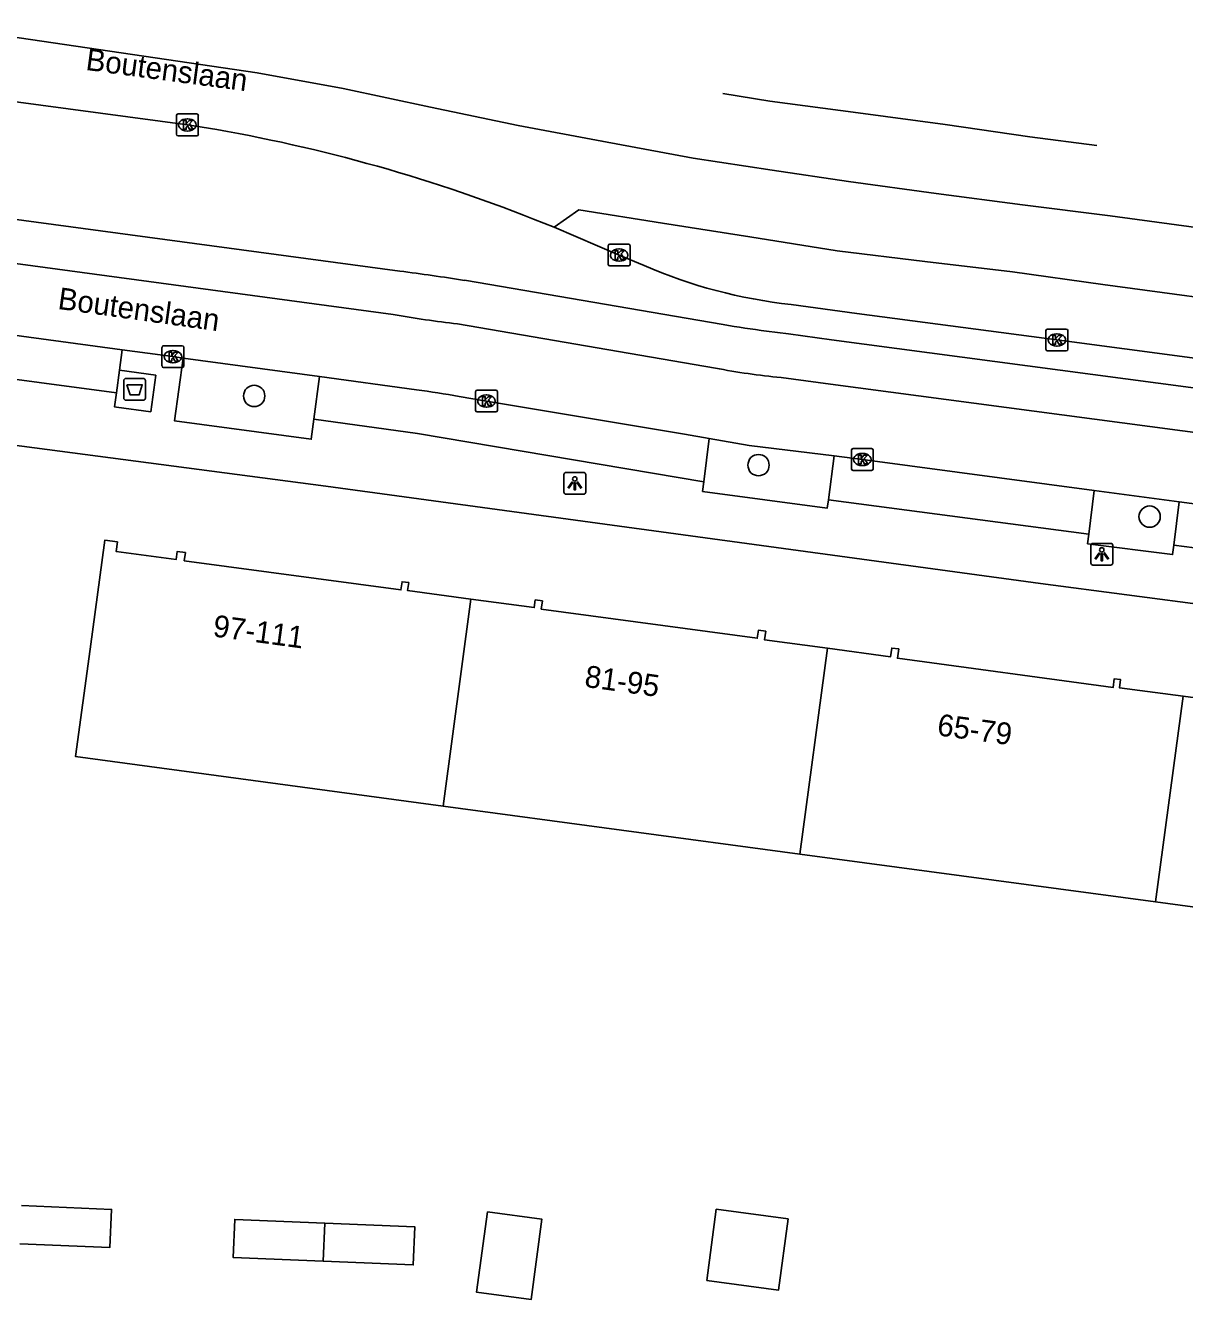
# Model space of a CAD drawing. Extents: x 161258 to 161838, y 380836 to 381727.
# Drawn here: x 161670.2 to 161723.3, y 381612.4 to 381670.8 of the extents above; entities that cross this region are included whole.
import ezdxf

# ---------------------------------------------------------------- set-up
doc = ezdxf.new("R2010")
doc.units = 0
for name, color, linetype in [('IMGEO_Afval_apart_plaats', 7, 'Continuous'), ('IMGEO_Boom', 7, 'Continuous'), ('IMGEO_Kolk', 7, 'Continuous'), ('IMGEO_Lichtpunt', 7, 'Continuous'), ('IMGEO_Openbare_ruimte_label', 7, 'Continuous'), ('IMGEO_Pand', 7, 'Continuous'), ('IMGEO_Pand_nummerreeks', 7, 'Continuous'), ('IMGEO_Parkeervlak_halfverhard', 7, 'Continuous'), ('IMGEO_Parkeervlak_open', 7, 'Continuous'), ('IMGEO_Rijbaan_lokaal_open', 7, 'Continuous'), ('IMGEO_Rijbaan_regionaal_gesloten', 7, 'Continuous'), ('IMGEO_Voetpad_gesloten', 7, 'Continuous'), ('IMGEO_Voetpad_open', 7, 'Continuous')]:
    doc.layers.add(name, color=color, linetype=linetype)

msp = doc.modelspace()

# ---------------------------------------------------------------- linework, layer by layer
at = {"layer": 'IMGEO_Afval_apart_plaats'}
for p, q in [((161674.752, 381653.736), (161674.752, 381654.536)), ((161674.752, 381654.536), (161674.752, 381653.736)), ((161674.852, 381654.636), (161675.642, 381654.636)), ((161675.642, 381654.636), (161674.852, 381654.636)), ((161675.742, 381654.536), (161675.742, 381653.736)), ((161675.742, 381653.736), (161675.742, 381654.536)), ((161675.642, 381653.636), (161674.852, 381653.636)), ((161674.852, 381653.636), (161675.642, 381653.636))]:
    msp.add_line(p, q, dxfattribs=at)
msp.add_lwpolyline([(161674.895, 381654.35), (161675.599, 381654.35), (161675.45, 381653.88), (161675.044, 381653.88), (161674.895, 381654.35)], dxfattribs=at)
for centre, start, end in [((161674.852, 381654.536), 90, 180), ((161674.852, 381654.536), 90, 180), ((161675.642, 381654.536), 0, 90), ((161675.642, 381654.536), 360, 90), ((161674.852, 381653.736), 180, 270), ((161674.852, 381653.736), 180, 270), ((161675.642, 381653.736), 270, 0), ((161675.642, 381653.736), 270, 0)]:
    msp.add_arc(centre, 0.1, start, end, dxfattribs=at)
at = {"layer": 'IMGEO_Boom'}
for centre in [(161680.724, 381653.834), (161703.825, 381650.663), (161721.741, 381648.304)]:
    msp.add_circle(centre, 0.489, dxfattribs=at)
at = {"layer": 'IMGEO_Kolk'}
for p, q in [((161677.165, 381665.828), (161677.165, 381666.68)), ((161677.24, 381666.754), (161678.092, 381666.754)), ((161678.166, 381666.68), (161678.166, 381665.828)), ((161677.653, 381666.534), (161677.678, 381666.534)), ((161678.092, 381665.754), (161677.24, 381665.754)), ((161677.676, 381665.974), (161677.651, 381665.974)), ((161696.94, 381659.864), (161696.94, 381660.716)), ((161697.015, 381660.79), (161697.867, 381660.79)), ((161697.428, 381660.57), (161697.453, 381660.57)), ((161697.941, 381660.716), (161697.941, 381659.864)), ((161697.867, 381659.79), (161697.015, 381659.79)), ((161697.451, 381660.01), (161697.426, 381660.01)), ((161716.992, 381655.974), (161716.992, 381656.826)), ((161717.067, 381656.9), (161717.919, 381656.9)), ((161717.993, 381656.826), (161717.993, 381655.974)), ((161717.48, 381656.68), (161717.505, 381656.68)), ((161676.502, 381655.209), (161676.502, 381656.061)), ((161676.577, 381656.135), (161677.429, 381656.135)), ((161676.99, 381655.915), (161677.015, 381655.915)), ((161677.503, 381656.061), (161677.503, 381655.209)), ((161717.919, 381655.9), (161717.067, 381655.9)), ((161717.503, 381656.12), (161717.478, 381656.12)), ((161677.429, 381655.135), (161676.577, 381655.135)), ((161677.013, 381655.355), (161676.988, 381655.355)), ((161690.863, 381653.174), (161690.863, 381654.026)), ((161690.938, 381654.1), (161691.79, 381654.1)), ((161691.351, 381653.88), (161691.376, 381653.88)), ((161691.864, 381654.026), (161691.864, 381653.174)), ((161691.374, 381653.32), (161691.349, 381653.32)), ((161691.79, 381653.1), (161690.938, 381653.1)), ((161708.08, 381650.497), (161708.08, 381651.349)), ((161708.155, 381651.423), (161709.007, 381651.423)), ((161708.568, 381651.203), (161708.593, 381651.203)), ((161709.081, 381651.349), (161709.081, 381650.497)), ((161709.007, 381650.423), (161708.155, 381650.423)), ((161708.591, 381650.643), (161708.566, 381650.643))]:
    msp.add_line(p, q, dxfattribs=at)
for points in [[(161677.165, 381665.828), (161677.165, 381666.68)], [(161677.24, 381666.754), (161678.092, 381666.754)], [(161678.166, 381666.68), (161678.166, 381665.828)], [(161677.486, 381666.454), (161677.609, 381666.454), (161677.609, 381666.303), (161677.739, 381666.454), (161677.903, 381666.454), (161677.757, 381666.303), (161677.91, 381666.054), (161677.758, 381666.054), (161677.673, 381666.218), (161677.609, 381666.151), (161677.609, 381666.054), (161677.486, 381666.054), (161677.486, 381666.454)], [(161678.092, 381665.754), (161677.24, 381665.754)], [(161696.94, 381659.864), (161696.94, 381660.716)], [(161697.015, 381660.79), (161697.867, 381660.79)], [(161697.261, 381660.49), (161697.384, 381660.49), (161697.384, 381660.339), (161697.514, 381660.49), (161697.678, 381660.49), (161697.532, 381660.339), (161697.685, 381660.09), (161697.533, 381660.09), (161697.448, 381660.254), (161697.384, 381660.187), (161697.384, 381660.09), (161697.261, 381660.09), (161697.261, 381660.49)], [(161697.941, 381660.716), (161697.941, 381659.864)], [(161697.867, 381659.79), (161697.015, 381659.79)], [(161716.992, 381655.974), (161716.992, 381656.826)], [(161717.067, 381656.9), (161717.919, 381656.9)], [(161717.993, 381656.826), (161717.993, 381655.974)], [(161717.313, 381656.6), (161717.436, 381656.6), (161717.436, 381656.449), (161717.566, 381656.6), (161717.73, 381656.6), (161717.584, 381656.449), (161717.737, 381656.2), (161717.585, 381656.2), (161717.5, 381656.364), (161717.436, 381656.297), (161717.436, 381656.2), (161717.313, 381656.2), (161717.313, 381656.6)], [(161676.502, 381655.209), (161676.502, 381656.061)], [(161676.577, 381656.135), (161677.429, 381656.135)], [(161676.823, 381655.835), (161676.946, 381655.835), (161676.946, 381655.684), (161677.076, 381655.835), (161677.24, 381655.835), (161677.094, 381655.684), (161677.247, 381655.435), (161677.095, 381655.435), (161677.01, 381655.599), (161676.946, 381655.532), (161676.946, 381655.435), (161676.823, 381655.435), (161676.823, 381655.835)], [(161677.503, 381656.061), (161677.503, 381655.209)], [(161717.919, 381655.9), (161717.067, 381655.9)], [(161677.429, 381655.135), (161676.577, 381655.135)], [(161690.863, 381653.174), (161690.863, 381654.026)], [(161690.938, 381654.1), (161691.79, 381654.1)], [(161691.864, 381654.026), (161691.864, 381653.174)], [(161691.184, 381653.8), (161691.307, 381653.8), (161691.307, 381653.649), (161691.437, 381653.8), (161691.601, 381653.8), (161691.455, 381653.649), (161691.608, 381653.4), (161691.456, 381653.4), (161691.371, 381653.564), (161691.307, 381653.497), (161691.307, 381653.4), (161691.184, 381653.4), (161691.184, 381653.8)], [(161691.79, 381653.1), (161690.938, 381653.1)], [(161708.08, 381650.497), (161708.08, 381651.349)], [(161708.155, 381651.423), (161709.007, 381651.423)], [(161708.401, 381651.123), (161708.524, 381651.123), (161708.524, 381650.972), (161708.654, 381651.123), (161708.818, 381651.123), (161708.672, 381650.972), (161708.825, 381650.723), (161708.673, 381650.723), (161708.588, 381650.887), (161708.524, 381650.82), (161708.524, 381650.723), (161708.401, 381650.723), (161708.401, 381651.123)], [(161709.081, 381651.349), (161709.081, 381650.497)], [(161709.007, 381650.423), (161708.155, 381650.423)]]:
    msp.add_lwpolyline(points, dxfattribs=at)
for centre, start, end in [((161677.242, 381666.678), 91.55205, 178.44795), ((161677.242, 381666.678), 91.55205, 178.44795), ((161678.09, 381666.678), 1.55205, 88.44795), ((161678.09, 381666.678), 1.55205, 88.44795), ((161677.242, 381665.83), 181.55205, 268.44795), ((161677.242, 381665.83), 181.55205, 268.44795), ((161678.09, 381665.83), 271.55205, 358.44795), ((161678.09, 381665.83), 271.55205, 358.44795), ((161697.017, 381660.714), 91.55205, 178.44795), ((161697.017, 381660.714), 91.55205, 178.44795), ((161697.865, 381660.714), 1.55205, 88.44795), ((161697.865, 381660.714), 1.55205, 88.44795), ((161697.017, 381659.866), 181.55205, 268.44795), ((161697.017, 381659.866), 181.55205, 268.44795), ((161697.865, 381659.866), 271.55205, 358.44795), ((161697.865, 381659.866), 271.55205, 358.44795), ((161717.069, 381656.824), 91.55205, 178.44795), ((161717.069, 381656.824), 91.55205, 178.44795), ((161717.917, 381656.824), 1.55205, 88.44795), ((161717.917, 381656.824), 1.55205, 88.44795), ((161676.579, 381656.059), 91.55205, 178.44795), ((161676.579, 381656.059), 91.55205, 178.44795), ((161677.427, 381656.059), 1.55205, 88.44795), ((161677.427, 381656.059), 1.55205, 88.44795), ((161717.069, 381655.976), 181.55205, 268.44795), ((161717.069, 381655.976), 181.55205, 268.44795), ((161717.917, 381655.976), 271.55205, 358.44795), ((161717.917, 381655.976), 271.55205, 358.44795), ((161676.579, 381655.211), 181.55205, 268.44795), ((161676.579, 381655.211), 181.55205, 268.44795), ((161677.427, 381655.211), 271.55205, 358.44795), ((161677.427, 381655.211), 271.55205, 358.44795), ((161690.94, 381654.024), 91.55205, 178.44795), ((161690.94, 381654.024), 91.55205, 178.44795), ((161691.788, 381654.024), 1.55205, 88.44795), ((161691.788, 381654.024), 1.55205, 88.44795), ((161690.94, 381653.176), 181.55205, 268.44795), ((161690.94, 381653.176), 181.55205, 268.44795), ((161691.788, 381653.176), 271.55205, 358.44795), ((161691.788, 381653.176), 271.55205, 358.44795), ((161708.157, 381651.347), 91.55205, 178.44795), ((161708.157, 381651.347), 91.55205, 178.44795), ((161709.005, 381651.347), 1.55205, 88.44795), ((161709.005, 381651.347), 1.55205, 88.44795), ((161708.157, 381650.499), 181.55205, 268.44795), ((161708.157, 381650.499), 181.55205, 268.44795), ((161709.005, 381650.499), 271.55205, 358.44795), ((161709.005, 381650.499), 271.55205, 358.44795)]:
    msp.add_arc(centre, 0.0765, start, end, dxfattribs=at)
for centre, major_axis, ratio, start_param, end_param in [((161677.652, 381666.254), (-0.387, 0.002), 0.722429, 4.712389, 7.853982), ((161677.677, 381666.254), (-0.39, 0.002), 0.717154, 1.570796, 4.712389), ((161697.427, 381660.29), (-0.387, 0.002), 0.722429, 4.712389, 7.853982), ((161697.452, 381660.29), (-0.39, 0.002), 0.717154, 1.570796, 4.712389), ((161717.479, 381656.4), (-0.387, 0.002), 0.722429, 4.712389, 7.853982), ((161717.504, 381656.4), (-0.39, 0.002), 0.717154, 1.570796, 4.712389), ((161676.989, 381655.635), (-0.387, 0.002), 0.722429, 4.712389, 7.853982), ((161677.014, 381655.635), (-0.39, 0.002), 0.717154, 1.570796, 4.712389), ((161691.35, 381653.6), (-0.387, 0.002), 0.722429, 4.712389, 7.853982), ((161691.375, 381653.6), (-0.39, 0.002), 0.717154, 1.570796, 4.712389), ((161708.567, 381650.923), (-0.387, 0.002), 0.722429, 4.712389, 7.853982), ((161708.592, 381650.923), (-0.39, 0.002), 0.717154, 1.570796, 4.712389)]:
    msp.add_ellipse(centre, major_axis=major_axis, ratio=ratio, start_param=start_param, end_param=end_param, dxfattribs=at)
at = {"layer": 'IMGEO_Lichtpunt'}
for p, q in [((161694.912, 381650.235), (161694.912, 381649.428)), ((161694.912, 381650.235), (161694.912, 381649.428)), ((161695.814, 381650.33), (161695.006, 381650.33)), ((161695.814, 381650.33), (161695.006, 381650.33)), ((161695.908, 381649.428), (161695.908, 381650.235)), ((161695.908, 381649.428), (161695.908, 381650.235)), ((161695.006, 381649.334), (161695.814, 381649.334)), ((161695.006, 381649.334), (161695.814, 381649.334)), ((161719.051, 381646.984), (161719.051, 381646.177)), ((161719.051, 381646.984), (161719.051, 381646.177)), ((161719.953, 381647.079), (161719.145, 381647.079)), ((161719.953, 381647.079), (161719.145, 381647.079)), ((161720.047, 381646.177), (161720.047, 381646.984)), ((161720.047, 381646.177), (161720.047, 381646.984)), ((161719.145, 381646.083), (161719.953, 381646.083)), ((161719.145, 381646.083), (161719.953, 381646.083))]:
    msp.add_line(p, q, dxfattribs=at)
for points in [[(161695.286, 381649.899), (161695.325, 381649.871), (161695.137, 381649.609), (161695.099, 381649.636), (161695.286, 381649.899)], [(161695.388, 381649.851), (161695.435, 381649.851), (161695.435, 381649.529), (161695.388, 381649.529), (161695.388, 381649.851)], [(161695.498, 381649.871), (161695.536, 381649.898), (161695.723, 381649.636), (161695.684, 381649.608), (161695.498, 381649.871)], [(161719.425, 381646.648), (161719.464, 381646.62), (161719.276, 381646.358), (161719.238, 381646.385), (161719.425, 381646.648)], [(161719.527, 381646.6), (161719.574, 381646.6), (161719.574, 381646.278), (161719.527, 381646.278), (161719.527, 381646.6)], [(161719.637, 381646.62), (161719.675, 381646.647), (161719.862, 381646.385), (161719.823, 381646.357), (161719.637, 381646.62)]]:
    msp.add_lwpolyline(points, dxfattribs=at)
for centre in [(161695.411, 381650.033), (161719.55, 381646.782)]:
    msp.add_circle(centre, 0.0994, dxfattribs=at)
for centre, start, end in [((161695.006, 381650.235), 90, 180), ((161695.006, 381650.235), 90, 180), ((161695.814, 381650.235), 0, 90), ((161695.814, 381650.235), 0, 90), ((161695.006, 381649.428), 180, 270), ((161695.006, 381649.428), 180, 270), ((161695.814, 381649.428), 270, 0), ((161695.814, 381649.428), 270, 360), ((161719.145, 381646.984), 90, 180), ((161719.145, 381646.984), 90, 180), ((161719.953, 381646.984), 0, 90), ((161719.953, 381646.984), 0, 90), ((161719.145, 381646.177), 180, 270), ((161719.145, 381646.177), 180, 270), ((161719.953, 381646.177), 270, 0), ((161719.953, 381646.177), 270, 360)]:
    msp.add_arc(centre, 0.0946, start, end, dxfattribs=at)
at = {"layer": 'IMGEO_Pand'}
for points in [[(161689.376, 381635.044), (161672.547, 381637.31), (161673.211, 381642.236), (161673.883, 381647.225), (161674.458, 381647.147), (161674.399, 381646.707), (161677.147, 381646.337), (161677.197, 381646.707), (161677.574, 381646.656), (161677.524, 381646.282), (161687.447, 381644.945), (161687.498, 381645.32), (161687.801, 381645.279), (161687.752, 381644.918), (161690.653, 381644.528)], [(161690.653, 381644.528), (161689.376, 381635.044)], [(161690.653, 381644.528), (161693.554, 381644.137), (161693.602, 381644.489), (161693.926, 381644.446), (161693.874, 381644.065), (161703.771, 381642.732), (161703.82, 381643.1), (161704.157, 381643.055), (161704.104, 381642.658), (161706.989, 381642.27)], [(161706.989, 381642.27), (161705.72, 381632.842)], [(161706.989, 381642.27), (161709.875, 381641.881), (161709.929, 381642.284), (161710.245, 381642.241), (161710.187, 381641.813), (161720.07, 381640.482), (161720.122, 381640.875), (161720.407, 381640.837), (161720.357, 381640.466), (161723.281, 381640.073)], [(161723.281, 381640.073), (161726.205, 381639.679), (161726.266, 381640.131), (161726.654, 381640.079), (161726.594, 381639.634), (161736.456, 381638.306), (161736.51, 381638.705), (161736.829, 381638.662), (161736.776, 381638.265), (161739.537, 381637.893), (161739.596, 381638.332), (161740.038, 381638.273), (161738.708, 381628.4), (161733.754, 381629.067), (161722.012, 381630.648)], [(161722.012, 381630.648), (161723.281, 381640.073)], [(161705.72, 381632.842), (161689.376, 381635.044)], [(161722.012, 381630.648), (161705.72, 381632.842)], [(161670.067, 381616.733), (161674.192, 381616.563), (161674.12, 381614.818), (161669.995, 381614.987)], [(161701.453, 381613.302), (161704.739, 381612.86), (161705.179, 381616.129), (161701.893, 381616.571), (161701.453, 381613.302)], [(161683.883, 381614.19), (161679.759, 381614.359), (161679.831, 381616.104), (161683.955, 381615.935)], [(161683.955, 381615.935), (161688.08, 381615.765), (161688.009, 381614.02), (161683.883, 381614.19)], [(161683.955, 381615.935), (161683.883, 381614.19)], [(161691.406, 381616.447), (161693.905, 381616.111), (161693.41, 381612.432), (161690.912, 381612.768), (161691.406, 381616.447)]]:
    msp.add_lwpolyline(points, dxfattribs=at)
at = {"layer": 'IMGEO_Parkeervlak_halfverhard'}
for points in [[(161591.581, 381672.404), (161665.053, 381662.56), (161687.397, 381659.556)], [(161690.364, 381659.132), (161702.211, 381657.106)], [(161704.19, 381656.809), (161705.202, 381656.678), (161707.162, 381656.402), (161745.844, 381651.267), (161745.561, 381649.28)]]:
    msp.add_lwpolyline(points, dxfattribs=at)
for centre, radius, start, end in [((161668.394, 381515.989), 144.819, 81.27429, 82.4601), ((161709.103, 381696.289), 39.785, 260.02386, 262.90612)]:
    msp.add_arc(centre, radius, start, end, dxfattribs=at)
at = {"layer": 'IMGEO_Parkeervlak_open'}
for points in [[(161683.714, 381654.721), (161683.461, 381652.77)], [(161701.316, 381649.903), (161701.559, 381651.889)], [(161707.027, 381649.08), (161707.291, 381651.084)], [(161718.952, 381647.508), (161719.195, 381649.505)], [(161723.091, 381648.984), (161722.845, 381647.001)]]:
    msp.add_lwpolyline(points, dxfattribs=at)
at = {"layer": 'IMGEO_Rijbaan_lokaal_open'}
for points in [[(161687.091, 381657.568), (161667.513, 381660.211)], [(161667.573, 381656.908), (161674.685, 381655.948)], [(161701.851, 381655.11), (161690.043, 381657.133)], [(161674.685, 381655.948), (161677.003, 381655.635), (161677.476, 381655.571)], [(161677.476, 381655.571), (161683.714, 381654.721)], [(161683.714, 381654.721), (161688.152, 381654.117)], [(161743.167, 381649.597), (161707.129, 381654.372), (161704.858, 381654.679)], [(161690.111, 381653.815), (161691.364, 381653.6), (161700.442, 381652.083), (161701.559, 381651.889)], [(161701.559, 381651.889), (161703.394, 381651.569), (161707.291, 381651.084)], [(161707.291, 381651.084), (161708.581, 381650.923), (161719.195, 381649.505)], [(161719.195, 381649.505), (161723.091, 381648.984)], [(161723.091, 381648.984), (161723.895, 381648.877), (161734.952, 381647.415)]]:
    msp.add_lwpolyline(points, dxfattribs=at)
for centre, radius, start, end in [((161696.347, 381710.147), 53.388, 260.01599, 263.21871), ((161707.649, 381684.859), 30.309, 258.97077, 264.71568), ((161680.11, 381595.444), 59.222, 80.27738, 82.19514)]:
    msp.add_arc(centre, radius, start, end, dxfattribs=at)
at = {"layer": 'IMGEO_Rijbaan_regionaal_gesloten'}
for points in [[(161679.007, 381666.04), (161677.666, 381666.255), (161657.266, 381668.988), (161618.127, 381674.239), (161615.451, 381674.598), (161596.053, 381677.191), (161575.643, 381679.932), (161555.208, 381682.652), (161534.802, 381685.416), (161514.402, 381688.138), (161500, 381690.051), (161493.724, 381690.885), (161474.493, 381693.446), (161433.673, 381698.93), (161413.286, 381701.641), (161412.199, 381701.786)], [(161668.901, 381670.395), (161680.859, 381668.646), (161684.795, 381667.916), (161688.805, 381667.074), (161692.816, 381666.233), (161696.656, 381665.513), (161700.839, 381664.728), (161704.447, 381664.184), (161707.95, 381663.655), (161711.965, 381663.118), (161715.913, 381662.59), (161719.934, 381662.085), (161723.875, 381661.551), (161728.04, 381661.015), (161732.012, 381660.466), (161735.99, 381659.958), (161752.017, 381657.797), (161760.062, 381656.742)], [(161702.189, 381667.689), (161704.351, 381667.34), (161708.386, 381666.804), (161712.371, 381666.274), (161716.253, 381665.701), (161719.327, 381665.313)], [(161817.985, 381645.977), (161809.404, 381647.011), (161803.595, 381647.872), (161795.685, 381648.9), (161787.775, 381649.927), (161779.72, 381650.974), (161771.676, 381652.109), (161763.62, 381653.148), (161755.563, 381654.187), (161747.855, 381655.181), (161741.235, 381656.106), (161737.26, 381656.662), (161731.03, 381657.39), (161727.522, 381657.865), (161719.602, 381658.939), (161715.452, 381659.519), (161711.437, 381660.002), (161707.421, 381660.485), (161703.427, 381661.121), (161699.432, 381661.756), (161695.592, 381662.368), (161694.46, 381661.561)], [(161698.584, 381659.806), (161697.441, 381660.29), (161694.46, 381661.561)], [(161751.562, 381651.859), (161748.27, 381652.294), (161735.854, 381653.957), (161717.493, 381656.402), (161708.326, 381657.615), (161705.319, 381658.026)]]:
    msp.add_lwpolyline(points, dxfattribs=at)
for centre, radius, start, end in [((161666.124, 381592.694), 74.469, 67.63445, 80.03744), ((161707.843, 381681.209), 23.32, 246.60568, 263.78579)]:
    msp.add_arc(centre, radius, start, end, dxfattribs=at)
at = {"layer": 'IMGEO_Voetpad_gesloten'}
for points in [[(161674.413, 381653.98), (161674.324, 381653.34), (161674.412, 381653.328), (161675.99, 381653.112), (161676.219, 381654.786), (161674.556, 381655.014)], [(161674.413, 381653.98), (161674.556, 381655.014)]]:
    msp.add_lwpolyline(points, dxfattribs=at)
at = {"layer": 'IMGEO_Voetpad_open'}
for points in [[(161599.202, 381661.023), (161611.247, 381659.449), (161663.105, 381652.447), (161684.01, 381649.696), (161716.743, 381645.239), (161740.472, 381642.131), (161745.302, 381641.497)], [(161674.556, 381655.014), (161674.685, 381655.948)], [(161677.476, 381655.571), (161677.074, 381652.701), (161683.342, 381651.854), (161683.461, 381652.77)], [(161667.325, 381654.926), (161674.413, 381653.98)], [(161683.461, 381652.77), (161688.212, 381652.107), (161701.316, 381649.903)], [(161701.316, 381649.903), (161701.262, 381649.458), (161706.977, 381648.699), (161707.027, 381649.08)], [(161718.952, 381647.508), (161707.027, 381649.08)], [(161722.845, 381647.001), (161722.791, 381646.567), (161718.897, 381647.059), (161718.952, 381647.508)], [(161734.683, 381645.463), (161722.845, 381647.001)]]:
    msp.add_lwpolyline(points, dxfattribs=at)

# ---------------------------------------------------------------- texts
at = {"layer": 'IMGEO_Openbare_ruimte_label'}
for rotation, p in [(352.41293, (161672.975, 381668.777)), (352.06445, (161671.695, 381657.826))]:
    msp.add_text('Boutenslaan', height=1, rotation=rotation, dxfattribs=at).set_placement(p)
at = {"layer": 'IMGEO_Pand_nummerreeks'}
for s, rotation, p in [('97-111', 352.295, (161678.799, 381642.82)), ('81-95', 352.08812, (161695.822, 381640.511)), ('65-79', 352.32552, (161711.973, 381638.287))]:
    msp.add_text(s, height=1, rotation=rotation, dxfattribs=at).set_placement(p)

doc.saveas('drawing.dxf')
